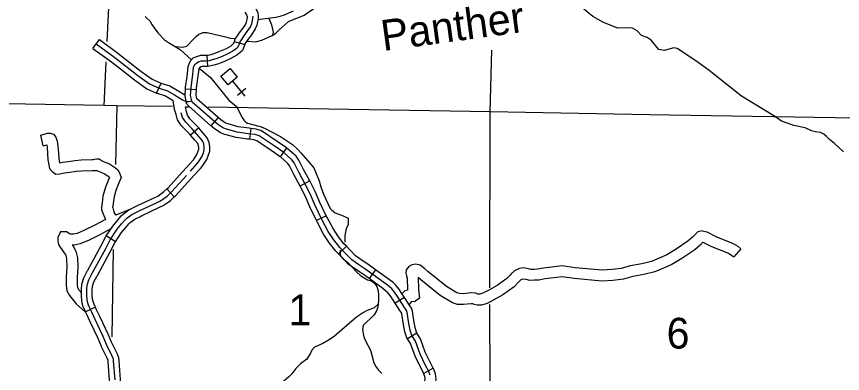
# Model space of a CAD drawing. Extents: x 0 to 3171, y 0 to 2059.
# Drawn here: x 1303.9 to 1493, y 1060.8 to 1142.5 of the extents above; entities that cross this region are included whole.
import ezdxf

# ---------------------------------------------------------------- set-up
doc = ezdxf.new("R2010")
doc.units = 0
for name, color, linetype in [('Level 32', 7, 'Continuous'), ('Level 35', 7, 'Continuous'), ('Level 4', 7, 'Continuous'), ('Level 45', 7, 'Continuous'), ('Level 46', 7, 'Continuous'), ('Level 5', 7, 'Continuous'), ('Level 57', 7, 'Continuous')]:
    doc.layers.add(name, color=color, linetype=linetype)

msp = doc.modelspace()

# ---------------------------------------------------------------- linework, layer by layer
at = {"layer": 'Level 32'}
for p, q in [((1353.74, 1136.74), (1356.14, 1136.06)), ((1347.47, 1133.58), (1347.6, 1131.08)), ((1342.51, 1125.95), (1345.01, 1125.79)), ((1350.06, 1119.35), (1348.41, 1117.48)), ((1357.55, 1116.87), (1357.23, 1114.39)), ((1365.69, 1112.44), (1364.26, 1110.39)), ((1371.02, 1104.87), (1368.82, 1103.69)), ((1374.8, 1096.88), (1372.55, 1095.78)), ((1379.41, 1089.9), (1377.62, 1088.15)), ((1386.07, 1084.54), (1384.61, 1082.51)), ((1392.69, 1078.22), (1390.59, 1076.86)), ((1395.54, 1070.04), (1393.43, 1068.7)), ((1399.31, 1062.05), (1397.13, 1060.82))]:
    msp.add_line(p, q, dxfattribs=at)
for points in [[(1358.26, 1144.83), (1358.8, 1143.99), (1359.14, 1143.31), (1359.25, 1142.57), (1359.19, 1141.96), (1359.05, 1141.3), (1358.88, 1140.49), (1358.56, 1139.64), (1357.66, 1138.3), (1356.85, 1137.25), (1356.41, 1136.53), (1356.2, 1136.27), (1356.14, 1136.06)], [(1357.99, 1142.54), (1357.95, 1142.15), (1357.83, 1141.55), (1357.67, 1140.84), (1357.44, 1140.21), (1356.65, 1139.03), (1355.82, 1137.96), (1355.38, 1137.25), (1355.07, 1136.85), (1354.91, 1136.3), (1354.71, 1135.83), (1354.56, 1135.47), (1354.28, 1135.2), (1353.61, 1134.68), (1352.43, 1134.01), (1350.85, 1133.3), (1349.5, 1132.79), (1348.72, 1132.55), (1347.97, 1132.35), (1347.18, 1132.31), (1346.19, 1132.31), (1345.64, 1132.16), (1345.08, 1131.76), (1344.65, 1131.44), (1344.49, 1131.13), (1344.37, 1130.73), (1344.1, 1128.59), (1343.78, 1126.22), (1343.66, 1124.4), (1343.92, 1123.21), (1344.14, 1122.9)], [(1356.16, 1143.47), (1356.63, 1142.74), (1356.73, 1142.55), (1356.73, 1142.51), (1356.71, 1142.33), (1356.61, 1141.81), (1356.47, 1141.2), (1356.32, 1140.78), (1355.63, 1139.76), (1354.79, 1138.67), (1354.37, 1138.08), (1353.94, 1137.44), (1353.74, 1136.74)], [(1353.74, 1136.74), (1353.73, 1136.72), (1353.57, 1136.32), (1353.51, 1136.19), (1353.45, 1136.14), (1352.92, 1135.73), (1351.86, 1135.13), (1350.37, 1134.46), (1349.1, 1133.97), (1348.38, 1133.75), (1347.77, 1133.59), (1347.47, 1133.58)], [(1356.14, 1136.06), (1356.09, 1135.89), (1355.86, 1135.33), (1355.6, 1134.75), (1355.11, 1134.25), (1354.3, 1133.64), (1352.99, 1132.9), (1351.33, 1132.15), (1349.91, 1131.6), (1349.05, 1131.35), (1348.16, 1131.11), (1347.6, 1131.08)], [(1347.47, 1133.58), (1347.15, 1133.56), (1346.01, 1133.56), (1345.09, 1133.3), (1344.27, 1132.97), (1343.67, 1132.28), (1343.33, 1131.59), (1343.15, 1130.99), (1342.86, 1128.75), (1342.54, 1126.34), (1342.51, 1125.95)], [(1347.6, 1131.08), (1347.21, 1131.06), (1346.36, 1131.06), (1346.19, 1131.01), (1345.82, 1130.75), (1345.65, 1130.62), (1345.6, 1130.47), (1345.34, 1128.42), (1345.03, 1126.09), (1345.01, 1125.79)], [(1342.51, 1125.95), (1342.41, 1124.31), (1342.75, 1122.7), (1343.31, 1121.96)], [(1345.01, 1125.79), (1344.92, 1124.49), (1345.09, 1123.73)], [(1350.06, 1119.35), (1345.09, 1123.73)], [(1348.41, 1117.48), (1343.31, 1121.96)], [(1398.6, 1060.42), (1398.23, 1061.42), (1397.54, 1062.64), (1396.3, 1065.23), (1395.24, 1068.18), (1394.4, 1069.5), (1394.03, 1070.68), (1393.7, 1072.21), (1393.34, 1074.72), (1393.16, 1075.24), (1392.94, 1075.6), (1392.68, 1075.93), (1391.62, 1077.57), (1391.09, 1078.42), (1390.41, 1079.43), (1389.79, 1080.16), (1389.2, 1080.71), (1388.5, 1081.25), (1383.62, 1084.77), (1382.29, 1085.66), (1380.67, 1086.79), (1379.31, 1088.21), (1377.92, 1089.64), (1376.56, 1091.36), (1375.27, 1093.32), (1373.88, 1095.9), (1372.16, 1099.41), (1371.13, 1101.95), (1370.08, 1103.98), (1368.52, 1106.9), (1367.42, 1108.99), (1366.96, 1109.69), (1365.09, 1111.34), (1362.88, 1112.88), (1359.45, 1115.17), (1358.5, 1115.48), (1356.96, 1115.68), (1354.4, 1116.04), (1351.95, 1116.71), (1351.16, 1116.98), (1349.88, 1117.85), (1344.14, 1122.9)], [(1357.23, 1114.39), (1356.8, 1114.44), (1354.15, 1114.81), (1351.58, 1115.52), (1350.6, 1115.85), (1349.11, 1116.86), (1348.41, 1117.48)], [(1357.55, 1116.87), (1357.13, 1116.92), (1354.65, 1117.26), (1352.32, 1117.9), (1351.72, 1118.11), (1350.64, 1118.84), (1350.06, 1119.35)], [(1365.69, 1112.44), (1363.59, 1113.91), (1360, 1116.3), (1358.78, 1116.71), (1357.55, 1116.87)], [(1364.26, 1110.39), (1362.18, 1111.84), (1358.9, 1114.03), (1358.22, 1114.26), (1357.23, 1114.39)], [(1371.02, 1104.87), (1369.62, 1107.49), (1368.5, 1109.63), (1367.91, 1110.52), (1365.87, 1112.32), (1365.69, 1112.44)], [(1368.82, 1103.69), (1367.41, 1106.32), (1366.35, 1108.35), (1366.01, 1108.86), (1364.32, 1110.35), (1364.26, 1110.39)], [(1374.8, 1096.88), (1373.3, 1099.93), (1372.26, 1102.47), (1371.19, 1104.57), (1371.02, 1104.87)], [(1372.55, 1095.78), (1371.02, 1098.9), (1369.99, 1101.43), (1368.97, 1103.4), (1368.82, 1103.69)], [(1379.41, 1089.9), (1378.86, 1090.46), (1377.58, 1092.09), (1376.35, 1093.96), (1374.99, 1096.47), (1374.8, 1096.88)], [(1377.62, 1088.15), (1376.98, 1088.81), (1375.55, 1090.63), (1374.2, 1092.67), (1372.77, 1095.33), (1372.55, 1095.78)], [(1386.07, 1084.54), (1384.33, 1085.79), (1383, 1086.69), (1381.49, 1087.74), (1380.21, 1089.08), (1379.41, 1089.9)], [(1384.61, 1082.51), (1382.9, 1083.74), (1381.59, 1084.63), (1379.85, 1085.83), (1378.41, 1087.35), (1377.62, 1088.15)], [(1392.69, 1078.22), (1392.67, 1078.25), (1392.14, 1079.1), (1391.41, 1080.18), (1390.7, 1081.03), (1390.01, 1081.66), (1389.25, 1082.25), (1386.07, 1084.54)], [(1390.59, 1076.86), (1390.56, 1076.9), (1390.04, 1077.74), (1389.41, 1078.68), (1388.89, 1079.29), (1388.39, 1079.75), (1387.75, 1080.25), (1384.61, 1082.51)], [(1395.54, 1070.03), (1395.24, 1071), (1394.93, 1072.43), (1394.56, 1075.03), (1394.29, 1075.77), (1393.97, 1076.31), (1393.69, 1076.67), (1392.69, 1078.22)], [(1393.43, 1068.7), (1393.25, 1068.98), (1392.82, 1070.36), (1392.47, 1071.98), (1392.12, 1074.42), (1392.02, 1074.71), (1391.91, 1074.89), (1391.66, 1075.2), (1390.59, 1076.86)], [(1397.13, 1060.82), (1396.43, 1062.06), (1395.15, 1064.74), (1394.11, 1067.63), (1393.43, 1068.7)], [(1399.31, 1062.05), (1398.65, 1063.22), (1397.46, 1065.71), (1396.37, 1068.73), (1395.54, 1070.04)], [(1401.02, 1053.3), (1400.36, 1053.85), (1397.88, 1055.68), (1397.39, 1056.63), (1397.23, 1057.87), (1397.42, 1059.55), (1397.37, 1060.14), (1397.09, 1060.89), (1397.13, 1060.82)], [(1402.63, 1055.21), (1401.91, 1055.82), (1399.83, 1057.35), (1399.81, 1057.39), (1399.75, 1057.89), (1399.93, 1059.52), (1399.83, 1060.7), (1399.37, 1061.94), (1399.31, 1062.05)]]:
    msp.add_lwpolyline(points, dxfattribs=at)
at = {"layer": 'Level 35'}
for points in [[(1356.62, 1136.87), (1357.03, 1136.83), (1358.63, 1136.69), (1360.08, 1137.08), (1362.45, 1138.14), (1363.23, 1138.68), (1363.93, 1139.4), (1366.17, 1141.32), (1369.71, 1142.81), (1372.73, 1144.87), (1374.89, 1146.09), (1375.59, 1146.37), (1376.81, 1146.53), (1378.02, 1146.41), (1380.82, 1145.22), (1381.85, 1145.02), (1382.63, 1145.18), (1383.44, 1145.44), (1384.33, 1145.68), (1385.24, 1145.77)], [(1493.21, 1111.56), (1491.12, 1113.44), (1490.02, 1114.33), (1489.33, 1115.07), (1488.7, 1115.59), (1487.95, 1115.93), (1486.83, 1116.08), (1485.91, 1116.3), (1484.4, 1117.03), (1481.87, 1117.54), (1479.05, 1118.58), (1477.67, 1119.53), (1469.85, 1124.25), (1462.46, 1130.13), (1459.96, 1131.99), (1455.77, 1134.83), (1455.1, 1135.16), (1454.36, 1135.31), (1452.12, 1134.68), (1450.97, 1134.98), (1450.22, 1135.75), (1449.2, 1137.09), (1448.29, 1137.72), (1446.95, 1138.12), (1446, 1139.21), (1444.89, 1139.79), (1443.54, 1139.9), (1441.52, 1139.81), (1438.3, 1141.13), (1435.86, 1142.46), (1433.26, 1144.65)], [(1333.32, 1142.53), (1333.71, 1142.14), (1334.39, 1141.54), (1334.9, 1140.63), (1335.38, 1139.92), (1336.21, 1138.78), (1337.78, 1137.16), (1338.69, 1136.52), (1339.84, 1135.89), (1341.39, 1134.94), (1344.03, 1132.54)], [(1361.64, 1142.06), (1362.28, 1140.62), (1362.66, 1138.93), (1362.52, 1138.18)], [(1340.48, 1135.66), (1341.93, 1135.48), (1342.87, 1135.68), (1344.41, 1137.29), (1345.03, 1137.95), (1345.66, 1138.42), (1346.64, 1138.86), (1347.55, 1138.87), (1351.74, 1137.84), (1352.83, 1137.57), (1353.94, 1137.46)], [(1345.69, 1130.66), (1348.3, 1128.56), (1352.48, 1123.33), (1354.25, 1121.87), (1355.54, 1119.38), (1355.99, 1118.69), (1356.39, 1118.29), (1356.79, 1118.05), (1359.66, 1117.29), (1360.67, 1116.93), (1364.29, 1115.06), (1367.07, 1113.18), (1368.2, 1112.14), (1369.09, 1111.19)], [(1369.09, 1111.19), (1371.99, 1107.86), (1373.2, 1104.86), (1373.56, 1103.5), (1374.14, 1101.84), (1375.72, 1098.59), (1376.08, 1098.14), (1376.84, 1097.59), (1378.71, 1096.88), (1379.85, 1096.33), (1379.81, 1094.88), (1379.38, 1093.87), (1379.08, 1092.41), (1379.06, 1090.82)], [(1377.98, 1089.05), (1377.98, 1088.78), (1378.01, 1088.15), (1378.17, 1087.6), (1378.64, 1087.04), (1379.65, 1086.25), (1381.81, 1083.97), (1382.75, 1083.16), (1384.21, 1082.25), (1385.19, 1081.97), (1385.84, 1081.45), (1386.37, 1080.72), (1386.66, 1079.72), (1386.76, 1078.83), (1386.77, 1077.5), (1386.61, 1076.06), (1386.34, 1075.1), (1385.76, 1074.21), (1383.28, 1071.75), (1383.1, 1070.75), (1383.44, 1069.15), (1383.84, 1068.1), (1384.9, 1066.1), (1385.73, 1063.24), (1386.13, 1062.36), (1386.79, 1061.52), (1387.5, 1060.8)], [(1386.68, 1076.68), (1385.77, 1075.85), (1384.18, 1075.24), (1383.33, 1074.79), (1381.75, 1073.71), (1376.72, 1069.36), (1375.47, 1068.51), (1374.01, 1067.64), (1372.08, 1066.82), (1371.49, 1066.14), (1371.18, 1065.44), (1370.37, 1064.09), (1368.94, 1062.97), (1367.87, 1061.95), (1366.92, 1060.7), (1366.17, 1059.92), (1364.7, 1058.73), (1364.1, 1057.98), (1363.56, 1057.48), (1360.93, 1056.15), (1359.6, 1054.56), (1358.28, 1053.84), (1356.58, 1051.47)]]:
    msp.add_lwpolyline(points, dxfattribs=at)
at = {"layer": 'Level 4'}
for points in [[(1412.34, 1120.69), (1412.67, 1134.83)], [(1339.64, 1121.87), (1326.86, 1122.08), (1323.88, 1122.13), (1238.61, 1123.6), (1236.05, 1123.64), (1149.56, 1125.14), (1147.91, 1125.2), (1123.96, 1126.06)], [(1412.34, 1120.69), (1347.74, 1121.74)], [(1412.25, 1080.41), (1412.34, 1120.69)], [(1536.04, 1118.5), (1501.62, 1119.16), (1500.67, 1119.17), (1448.77, 1120), (1412.34, 1120.69)], [(1412.4, 1040.1), (1412.25, 1076.6)]]:
    msp.add_lwpolyline(points, dxfattribs=at)
at = {"layer": 'Level 45'}
for p, q in [((1321.39, 1135.2), (1322.86, 1137.23)), ((1335.97, 1124.98), (1336.99, 1127.26)), ((1345.6, 1116.98), (1343.72, 1115.32)), ((1339.98, 1101.19), (1338.27, 1103.02)), ((1326.54, 1090.9), (1324.45, 1092.27)), ((1321.95, 1075.97), (1319.68, 1074.92))]:
    msp.add_line(p, q, dxfattribs=at)
for points in [[(1367.21, 1143.74), (1366.82, 1143.56), (1365.13, 1142.84), (1364.17, 1142.47), (1363.24, 1142.25), (1359.67, 1141.81), (1359.16, 1141.77)], [(1322.86, 1137.23), (1327.12, 1134.14), (1329.94, 1131.92)], [(1321.39, 1135.2), (1325.62, 1132.14), (1328.39, 1129.96)], [(1322.12, 1136.21), (1326.37, 1133.14), (1331.64, 1128.99), (1334.36, 1127.08), (1336.52, 1126.1), (1338.47, 1125.47), (1340.04, 1124.59), (1341.89, 1123.42), (1342.34, 1123.23), (1342.87, 1123.08), (1343.43, 1123.07), (1343.92, 1123.21)], [(1329.94, 1131.92), (1332.39, 1129.99), (1334.98, 1128.17), (1336.99, 1127.26)], [(1328.39, 1129.96), (1330.89, 1127.98), (1333.74, 1125.98), (1335.97, 1124.98)], [(1336.97, 1127.27), (1338.98, 1126.62), (1340.68, 1125.66), (1342.42, 1124.56)], [(1335.97, 1124.98), (1336.07, 1124.94), (1337.97, 1124.32), (1339.4, 1123.52), (1339.79, 1123.26)], [(1343.72, 1115.32), (1343.11, 1116.02), (1341.67, 1117.51), (1340.76, 1118.84), (1340.41, 1120.1), (1340.06, 1121.19), (1339.79, 1123.26)], [(1345.6, 1116.98), (1344.94, 1117.72), (1343.61, 1119.09), (1343.06, 1119.9), (1342.82, 1120.77), (1342.58, 1121.83)], [(1342.58, 1121.83), (1343.47, 1121.82)], [(1343.7, 1107.08), (1345.43, 1108.97), (1346.32, 1110.36), (1346.69, 1111.29), (1346.88, 1111.88), (1346.88, 1112.56), (1346.76, 1113.33), (1346.44, 1114.06), (1345.69, 1114.98), (1344.02, 1116.87), (1342.64, 1118.3), (1341.91, 1119.37), (1341.62, 1120.43)], [(1309.97, 1112.91), (1309.43, 1115.31), (1310.98, 1115.78), (1311.59, 1115.78), (1312.33, 1115.57), (1312.93, 1114.87), (1313.19, 1113.94), (1313.39, 1112.84), (1313.48, 1111.33), (1313.57, 1110), (1313.73, 1109.04), (1313.73, 1109.02), (1314.45, 1109.16), (1315.77, 1109.34), (1317.26, 1109.55), (1318.67, 1109.67), (1321.23, 1109.75), (1321.5, 1109.75), (1321.71, 1109.86), (1322.17, 1109.91), (1322.82, 1109.91), (1323.54, 1109.43), (1323.99, 1109.23), (1325.16, 1108.75), (1326.54, 1107.86), (1327.06, 1107.37), (1327.49, 1106.74), (1327.82, 1105.68), (1327.19, 1104.08), (1326.66, 1102.64), (1326.15, 1100.93), (1326.01, 1099.59), (1325.9, 1098.8), (1325.96, 1098.74), (1326.07, 1098.12), (1326.29, 1097.44), (1326.6, 1097.02)], [(1346, 1107.74), (1346.42, 1108.2), (1347.44, 1109.79), (1347.86, 1110.87), (1348.13, 1111.67), (1348.13, 1112.65), (1347.97, 1113.68), (1347.52, 1114.71), (1346.65, 1115.79), (1345.6, 1116.98)], [(1344.15, 1109.43), (1344.43, 1109.73), (1345.2, 1110.93), (1345.51, 1111.72), (1345.63, 1112.08), (1345.63, 1112.46), (1345.55, 1112.98), (1345.37, 1113.4), (1344.74, 1114.17), (1343.72, 1115.32)], [(1309.97, 1112.91), (1310.8, 1113.12), (1310.91, 1112.54), (1310.99, 1111.18), (1311.08, 1109.71), (1311.27, 1108.57), (1311.46, 1107.72), (1312.02, 1107.03), (1312.91, 1106.42), (1313.84, 1106.48), (1314.87, 1106.7), (1316.11, 1106.87), (1317.54, 1107.07), (1318.81, 1107.18), (1321.31, 1107.25), (1322.17, 1107.27), (1322.22, 1107.3), (1322.32, 1107.23), (1323.01, 1106.92), (1324, 1106.52), (1325, 1105.88), (1325.14, 1105.74), (1325.15, 1105.73), (1324.86, 1104.97), (1324.29, 1103.43), (1323.69, 1101.41), (1323.53, 1099.89), (1323.38, 1098.81), (1323.38, 1098.27), (1324.29, 1096.06)], [(1338.27, 1103.02), (1338.58, 1103.3), (1341.9, 1106.96), (1342.78, 1107.93), (1344.15, 1109.43)], [(1339.98, 1101.19), (1340.36, 1101.55), (1343.75, 1105.28), (1344.63, 1106.24), (1346, 1107.74)], [(1326.46, 1059.35), (1326.12, 1063.6), (1326.07, 1064.07), (1325.82, 1064.77), (1324.52, 1067.41), (1323.72, 1069.28), (1321.91, 1073.17), (1321.1, 1074.82), (1320.67, 1075.76), (1320.3, 1076.68), (1320.08, 1077.65), (1319.99, 1078.76), (1319.99, 1079.93), (1320.08, 1080.99), (1320.47, 1082.25), (1321.25, 1083.75), (1324.33, 1089.37), (1325.34, 1091.36), (1326.94, 1093.8), (1327.96, 1095.02), (1328.74, 1095.96), (1329.17, 1096.33), (1330.29, 1097.15), (1331.98, 1098.02), (1336.13, 1099.96), (1336.85, 1100.31), (1337.65, 1100.86), (1338.35, 1101.38), (1339.47, 1102.42), (1342.83, 1106.12)], [(1330.95, 1098.9), (1331.43, 1099.15), (1335.59, 1101.09), (1336.22, 1101.4), (1336.93, 1101.88), (1337.55, 1102.34), (1338.27, 1103.02)], [(1332.09, 1096.67), (1332.53, 1096.9), (1336.66, 1098.83), (1337.48, 1099.23), (1338.38, 1099.84), (1339.16, 1100.42), (1339.98, 1101.19)], [(1324.45, 1092.27), (1325.94, 1094.55), (1327, 1095.81), (1327.84, 1096.85), (1328.4, 1097.31), (1329.62, 1098.22), (1330.95, 1098.9)], [(1326.54, 1090.9), (1327.95, 1093.06), (1328.92, 1094.22), (1329.63, 1095.08), (1329.94, 1095.34), (1330.95, 1096.09), (1332.09, 1096.67)], [(1329.62, 1098.22), (1326.6, 1097.02)], [(1324.29, 1096.06), (1321.86, 1094.76), (1319.46, 1093.61), (1317.77, 1092.85), (1316.86, 1092.7), (1316.27, 1092.7), (1316.04, 1092.77), (1315.92, 1092.87), (1315.31, 1093.24), (1313.94, 1093.24), (1313.37, 1091.9), (1313.37, 1091.2), (1313.52, 1090.29), (1313.87, 1089.68), (1314.26, 1089.18), (1314.75, 1088.51), (1315.16, 1087.84), (1315.37, 1086.94), (1315.42, 1085.27), (1315.27, 1082.74), (1315.27, 1080.98), (1315.4, 1079.73), (1316.02, 1078.64), (1317.57, 1076.71), (1319.69, 1074.83)], [(1325.49, 1093.87), (1323, 1092.53), (1320.51, 1091.34), (1318.5, 1090.44), (1317.07, 1090.2), (1316.61, 1090.2), (1316.83, 1089.9), (1317.5, 1088.81), (1317.87, 1087.27), (1317.92, 1085.23), (1317.77, 1082.67), (1317.77, 1081.11), (1317.84, 1080.51), (1318.1, 1080.04), (1318.74, 1079.25)], [(1320.2, 1084.45), (1323.22, 1089.95), (1324.26, 1091.98), (1324.45, 1092.27)], [(1322.4, 1083.25), (1325.43, 1088.78), (1326.43, 1090.73), (1326.54, 1090.9)], [(1319.68, 1074.92), (1319.52, 1075.27), (1319.1, 1076.31), (1318.85, 1077.46), (1318.74, 1078.71), (1318.74, 1079.99), (1318.85, 1081.23), (1319.31, 1082.72), (1320.14, 1084.34), (1320.2, 1084.45)], [(1321.95, 1075.97), (1321.82, 1076.25), (1321.5, 1077.05), (1321.32, 1077.84), (1321.24, 1078.82), (1321.24, 1079.87), (1321.32, 1080.75), (1321.63, 1081.78), (1322.35, 1083.17), (1322.4, 1083.25)], [(1325.65, 1067.95), (1324.86, 1069.79), (1323.04, 1073.71), (1322.23, 1075.36), (1321.95, 1075.97)], [(1323.35, 1066.96), (1322.58, 1068.77), (1320.78, 1072.63), (1319.97, 1074.29), (1319.68, 1074.92)], [(1325.23, 1058.94), (1325.21, 1059.26), (1324.88, 1063.48), (1324.84, 1063.78), (1324.67, 1064.28), (1323.38, 1066.89), (1323.35, 1066.96)], [(1327.73, 1059.11), (1327.71, 1059.44), (1327.37, 1063.73), (1327.29, 1064.35), (1326.98, 1065.25), (1325.66, 1067.94), (1325.65, 1067.95)]]:
    msp.add_lwpolyline(points, dxfattribs=at)
at = {"layer": 'Level 46'}
for points in [[(1460.82, 1093.46), (1459.88, 1093.25), (1458.65, 1091.99), (1457.61, 1091.08), (1454.88, 1089.23), (1452.77, 1087.98), (1451.01, 1087.21), (1449.23, 1086.43), (1447.02, 1085.89), (1444.36, 1085.43), (1442.34, 1084.81), (1440.22, 1084.56), (1437.96, 1084.46), (1431.81, 1085.01), (1428.84, 1085.44), (1424.53, 1084.91), (1423.16, 1084.65), (1422.36, 1084.62), (1421.62, 1084.61), (1421.07, 1084.73), (1419.93, 1084.95), (1419.05, 1084.85), (1417.87, 1084.32), (1417.17, 1083.59), (1416.89, 1083.33), (1416.13, 1082.54), (1413.91, 1080.9), (1412, 1079.86), (1410.67, 1079.15), (1409.96, 1078.93), (1409.6, 1078.92), (1409.5, 1078.95), (1409.02, 1079.18), (1407.97, 1079.26), (1406.12, 1079.05), (1405.27, 1079.07), (1404.73, 1079.24), (1402.31, 1080.72), (1398.08, 1084.17), (1397.34, 1084.78), (1396.33, 1085.56), (1395.3, 1085.79), (1394.43, 1085.65), (1393.7, 1085.27), (1393.13, 1084.55), (1393.03, 1083.74), (1393.15, 1083.12), (1393.32, 1082.61), (1393.42, 1079.98), (1393.43, 1079.85), (1392.79, 1079.71), (1392.15, 1079.07)], [(1460.82, 1093.46), (1461.96, 1093.2), (1464.02, 1092.16), (1467.94, 1090.55), (1469.05, 1089.93), (1469.71, 1089.35), (1468.07, 1087.46)], [(1461.04, 1090.86), (1460.37, 1090.17), (1459.14, 1089.09), (1456.22, 1087.12), (1453.92, 1085.75), (1452.02, 1084.92), (1450.03, 1084.05), (1447.53, 1083.44), (1444.95, 1082.99), (1442.86, 1082.35), (1440.42, 1082.07), (1437.9, 1081.95), (1431.52, 1082.52), (1428.81, 1082.91), (1424.91, 1082.43), (1423.44, 1082.16), (1422.44, 1082.12), (1421.38, 1082.1), (1420.56, 1082.28), (1419.82, 1082.42), (1419.73, 1082.41), (1419.34, 1082.24), (1418.92, 1081.81), (1418.64, 1081.55), (1417.79, 1080.65), (1415.25, 1078.79), (1413.19, 1077.66), (1411.63, 1076.83), (1410.36, 1076.44), (1409.34, 1076.42), (1408.66, 1076.58), (1408.36, 1076.72), (1408.01, 1076.75), (1406.24, 1076.55), (1404.85, 1076.57), (1403.67, 1076.96), (1400.86, 1078.67), (1396.49, 1082.24), (1395.82, 1082.79), (1395.91, 1080.17), (1396.01, 1079.37), (1396.11, 1078.07), (1395.03, 1077.21), (1394.34, 1077.28), (1394.34, 1077.25), (1393.77, 1076.56)], [(1461.04, 1090.86), (1462.98, 1089.88), (1466.85, 1088.3), (1467.59, 1087.88), (1468.07, 1087.46)]]:
    msp.add_lwpolyline(points, dxfattribs=at)
at = {"layer": 'Level 5'}
for points in [[(1328.48, 1210.5), (1326.1, 1168.05), (1324.59, 1136.74)], [(1324.36, 1132.12), (1323.88, 1122.13)], [(1326.86, 1122.08), (1326.52, 1108.6)], [(1326.03, 1089.19), (1325.69, 1069.2)]]:
    msp.add_lwpolyline(points, dxfattribs=at)
at = {"layer": 'Level 57'}
for p, q in [((1356.23, 1124.25), (1353.38, 1127.72)), ((1356.4, 1126.01), (1354.47, 1124.43))]:
    msp.add_line(p, q, dxfattribs=at)
msp.add_lwpolyline([(1352.78, 1130.59), (1354.43, 1128.58), (1352.34, 1126.87), (1350.69, 1128.88)], close=True, dxfattribs=at)

# ---------------------------------------------------------------- texts
at = {"layer": 'Level 35'}
msp.add_text('Panther', height=7.04, rotation=7.7348, dxfattribs=at).set_placement((1387.82, 1134.59))
at = {"layer": 'Level 5'}
for s, p in [('1', (1366.16, 1071.85)), ('6', (1452.72, 1066.5))]:
    msp.add_text(s, height=7.04, dxfattribs=at).set_placement(p)

doc.saveas('drawing.dxf')
